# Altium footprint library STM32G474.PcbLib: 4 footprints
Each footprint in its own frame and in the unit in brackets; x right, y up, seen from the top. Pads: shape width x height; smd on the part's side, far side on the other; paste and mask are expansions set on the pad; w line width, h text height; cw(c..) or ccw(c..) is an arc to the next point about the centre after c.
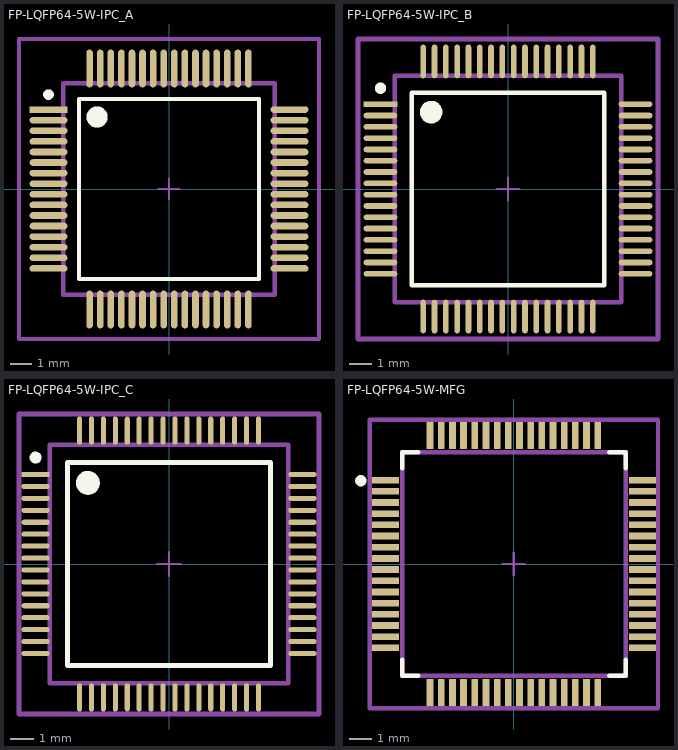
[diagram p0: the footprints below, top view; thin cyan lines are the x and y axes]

## FP-LQFP64-5W-IPC_A [mm]
pads (64):
  rect 1.788x0.312 smd paste+0 mask+0: 1(-5.691,3.75)
  rrect100% 1.788x0.312 smd paste+0 mask+0: 2(-5.691,3.25) 3(-5.691,2.75) 4(-5.691,2.25) 5(-5.691,1.75) 6(-5.691,1.25) 7(-5.691,0.75) 8(-5.691,0.25) 9(-5.691,-0.25) 10(-5.691,-0.75) 11(-5.691,-1.25) 12(-5.691,-1.75) 13(-5.691,-2.25) 14(-5.691,-2.75) 15(-5.691,-3.25) 16(-5.691,-3.75) 33(5.691,-3.75) 34(5.691,-3.25) 35(5.691,-2.75) 36(5.691,-2.25) 37(5.691,-1.75) 38(5.691,-1.25) 39(5.691,-0.75) 40(5.691,-0.25) 41(5.691,0.25) 42(5.691,0.75) 43(5.691,1.25) 44(5.691,1.75) 45(5.691,2.25) 46(5.691,2.75) 47(5.691,3.25) 48(5.691,3.75)
  rrect100% 0.312x1.788 smd paste+0 mask+0: 17(-3.75,-5.691) 18(-3.25,-5.691) 19(-2.75,-5.691) 20(-2.25,-5.691) 21(-1.75,-5.691) 22(-1.25,-5.691) 23(-0.75,-5.691) 24(-0.25,-5.691) 25(0.25,-5.691) 26(0.75,-5.691) 27(1.25,-5.691) 28(1.75,-5.691) 29(2.25,-5.691) 30(2.75,-5.691) 31(3.25,-5.691) 32(3.75,-5.691) 49(3.75,5.691) 50(3.25,5.691) 51(2.75,5.691) 52(2.25,5.691) 53(1.75,5.691) 54(1.25,5.691) 55(0.75,5.691) 56(0.25,5.691) 57(-0.25,5.691) 58(-0.75,5.691) 59(-1.25,5.691) 60(-1.75,5.691) 61(-2.25,5.691) 62(-2.75,5.691) 63(-3.25,5.691) 64(-3.75,5.691)
Top Overlay:
  circle w0.25: c-5.691,4.46 r0.125
  circle w0.5: c-3.4,3.4 r0.25
  lines w0.2: -4.25,-4.25 4.25,-4.25 4.25,4.25 -4.25,4.25 -4.25,-4.25
Top Assembly:
  lines w0.2: -7.085,-7.085 7.085,-7.085 7.085,7.085 -7.085,7.085 -7.085,-7.085
  text ".Designator" at 0,0 h1
Top 3D Body:
  lines w0.2: -5,-5 5,-5 5,5 -5,5 -5,-5
Top Courtyard:
  lines w0.2: -7.085,-7.085 7.085,-7.085 7.085,7.085 -7.085,7.085 -7.085,-7.085
Top Component Center:
  lines w0.1: -0.5,0 0.5,0 ; 0,-0.5 0,0.5
3D body "IC_STMicroelectronics_STM32L431RCT6_eec.STEP": height 0.25, standoff 0, extent -7.085,-7.085 7.085,7.085

## FP-LQFP64-5W-IPC_B [mm]
pads (64):
  rect 1.488x0.252 smd paste+0 mask+0: 1(-5.641,3.75)
  rrect100% 1.488x0.252 smd paste+0 mask+0: 2(-5.641,3.25) 3(-5.641,2.75) 4(-5.641,2.25) 5(-5.641,1.75) 6(-5.641,1.25) 7(-5.641,0.75) 8(-5.641,0.25) 9(-5.641,-0.25) 10(-5.641,-0.75) 11(-5.641,-1.25) 12(-5.641,-1.75) 13(-5.641,-2.25) 14(-5.641,-2.75) 15(-5.641,-3.25) 16(-5.641,-3.75) 33(5.641,-3.75) 34(5.641,-3.25) 35(5.641,-2.75) 36(5.641,-2.25) 37(5.641,-1.75) 38(5.641,-1.25) 39(5.641,-0.75) 40(5.641,-0.25) 41(5.641,0.25) 42(5.641,0.75) 43(5.641,1.25) 44(5.641,1.75) 45(5.641,2.25) 46(5.641,2.75) 47(5.641,3.25) 48(5.641,3.75)
  rrect100% 0.252x1.488 smd paste+0 mask+0: 17(-3.75,-5.641) 18(-3.25,-5.641) 19(-2.75,-5.641) 20(-2.25,-5.641) 21(-1.75,-5.641) 22(-1.25,-5.641) 23(-0.75,-5.641) 24(-0.25,-5.641) 25(0.25,-5.641) 26(0.75,-5.641) 27(1.25,-5.641) 28(1.75,-5.641) 29(2.25,-5.641) 30(2.75,-5.641) 31(3.25,-5.641) 32(3.75,-5.641) 49(3.75,5.641) 50(3.25,5.641) 51(2.75,5.641) 52(2.25,5.641) 53(1.75,5.641) 54(1.25,5.641) 55(0.75,5.641) 56(0.25,5.641) 57(-0.25,5.641) 58(-0.75,5.641) 59(-1.25,5.641) 60(-1.75,5.641) 61(-2.25,5.641) 62(-2.75,5.641) 63(-3.25,5.641) 64(-3.75,5.641)
Top Overlay:
  circle w0.25: c-5.641,4.46 r0.125
  circle w0.5: c-3.4,3.4 r0.25
  lines w0.2: -4.25,-4.25 4.25,-4.25 4.25,4.25 -4.25,4.25 -4.25,-4.25
Top Assembly:
  lines w0.2: -6.635,-6.635 6.635,-6.635 6.635,6.635 -6.635,6.635 -6.635,-6.635
  text ".Designator" at 0,0 h1
Top 3D Body:
  lines w0.2: -5,-5 5,-5 5,5 -5,5 -5,-5
Top Courtyard:
  lines w0.2: -6.635,-6.635 6.635,-6.635 6.635,6.635 -6.635,6.635 -6.635,-6.635
Top Component Center:
  lines w0.1: -0.5,0 0.5,0 ; 0,-0.5 0,0.5
3D body "IC_STMicroelectronics_STM32L431RCT6_eec.STEP": height 0.25, standoff 0, extent -6.635,-6.635 6.635,6.635

## FP-LQFP64-5W-IPC_C [mm]
pads (64):
  rect 1.188x0.212 smd paste+0 mask+0: 1(-5.591,3.75)
  rrect100% 1.188x0.212 smd paste+0 mask+0: 2(-5.591,3.25) 3(-5.591,2.75) 4(-5.591,2.25) 5(-5.591,1.75) 6(-5.591,1.25) 7(-5.591,0.75) 8(-5.591,0.25) 9(-5.591,-0.25) 10(-5.591,-0.75) 11(-5.591,-1.25) 12(-5.591,-1.75) 13(-5.591,-2.25) 14(-5.591,-2.75) 15(-5.591,-3.25) 16(-5.591,-3.75) 33(5.591,-3.75) 34(5.591,-3.25) 35(5.591,-2.75) 36(5.591,-2.25) 37(5.591,-1.75) 38(5.591,-1.25) 39(5.591,-0.75) 40(5.591,-0.25) 41(5.591,0.25) 42(5.591,0.75) 43(5.591,1.25) 44(5.591,1.75) 45(5.591,2.25) 46(5.591,2.75) 47(5.591,3.25) 48(5.591,3.75)
  rrect100% 0.212x1.188 smd paste+0 mask+0: 17(-3.75,-5.591) 18(-3.25,-5.591) 19(-2.75,-5.591) 20(-2.25,-5.591) 21(-1.75,-5.591) 22(-1.25,-5.591) 23(-0.75,-5.591) 24(-0.25,-5.591) 25(0.25,-5.591) 26(0.75,-5.591) 27(1.25,-5.591) 28(1.75,-5.591) 29(2.25,-5.591) 30(2.75,-5.591) 31(3.25,-5.591) 32(3.75,-5.591) 49(3.75,5.591) 50(3.25,5.591) 51(2.75,5.591) 52(2.25,5.591) 53(1.75,5.591) 54(1.25,5.591) 55(0.75,5.591) 56(0.25,5.591) 57(-0.25,5.591) 58(-0.75,5.591) 59(-1.25,5.591) 60(-1.75,5.591) 61(-2.25,5.591) 62(-2.75,5.591) 63(-3.25,5.591) 64(-3.75,5.591)
Top Overlay:
  circle w0.25: c-5.591,4.46 r0.125
  circle w0.5: c-3.4,3.4 r0.25
  lines w0.2: -4.25,-4.25 4.25,-4.25 4.25,4.25 -4.25,4.25 -4.25,-4.25
Top Assembly:
  lines w0.2: -6.285,-6.285 6.285,-6.285 6.285,6.285 -6.285,6.285 -6.285,-6.285
  text ".Designator" at 0,0 h1
Top 3D Body:
  lines w0.2: -5,-5 5,-5 5,5 -5,5 -5,-5
Top Courtyard:
  lines w0.2: -6.285,-6.285 6.285,-6.285 6.285,6.285 -6.285,6.285 -6.285,-6.285
Top Component Center:
  lines w0.1: -0.5,0 0.5,0 ; 0,-0.5 0,0.5
3D body "IC_STMicroelectronics_STM32L431RCT6_eec.STEP": height 0.25, standoff 0, extent -6.285,-6.285 6.285,6.285

## FP-LQFP64-5W-MFG [mm]
pads (64):
  rect 1.2x0.3 smd paste+0 mask+0: 1(-5.75,3.75) 2(-5.75,3.25) 3(-5.75,2.75) 4(-5.75,2.25) 5(-5.75,1.75) 6(-5.75,1.25) 7(-5.75,0.75) 8(-5.75,0.25) 9(-5.75,-0.25) 10(-5.75,-0.75) 11(-5.75,-1.25) 12(-5.75,-1.75) 13(-5.75,-2.25) 14(-5.75,-2.75) 15(-5.75,-3.25) 16(-5.75,-3.75) 33(5.75,-3.75) 34(5.75,-3.25) 35(5.75,-2.75) 36(5.75,-2.25) 37(5.75,-1.75) 38(5.75,-1.25) 39(5.75,-0.75) 40(5.75,-0.25) 41(5.75,0.25) 42(5.75,0.75) 43(5.75,1.25) 44(5.75,1.75) 45(5.75,2.25) 46(5.75,2.75) 47(5.75,3.25) 48(5.75,3.75)
  rect 0.3x1.2 smd paste+0 mask+0: 17(-3.75,-5.75) 18(-3.25,-5.75) 19(-2.75,-5.75) 20(-2.25,-5.75) 21(-1.75,-5.75) 22(-1.25,-5.75) 23(-0.75,-5.75) 24(-0.25,-5.75) 25(0.25,-5.75) 26(0.75,-5.75) 27(1.25,-5.75) 28(1.75,-5.75) 29(2.25,-5.75) 30(2.75,-5.75) 31(3.25,-5.75) 32(3.75,-5.75) 49(3.75,5.75) 50(3.25,5.75) 51(2.75,5.75) 52(2.25,5.75) 53(1.75,5.75) 54(1.25,5.75) 55(0.75,5.75) 56(0.25,5.75) 57(-0.25,5.75) 58(-0.75,5.75) 59(-1.25,5.75) 60(-1.75,5.75) 61(-2.25,5.75) 62(-2.75,5.75) 63(-3.25,5.75) 64(-3.75,5.75)
Top Overlay:
  circle w0.25: c-6.85,3.725 r0.125
  lines w0.2: -5,-4.275 -5,-5 -4.275,-5 ; -5,4.275 -5,5 -4.275,5 ; 4.275,-5 5,-5 5,-4.275 ; 4.275,5 5,5 5,4.275
Top Assembly:
  lines w0.2: -6.45,-6.45 6.45,-6.45 6.45,6.45 -6.45,6.45 -6.45,-6.45
  text ".Designator" at 0,0.188 h1
Top 3D Body:
  lines w0.2: -5,-5 5,-5 5,5 -5,5 -5,-5
Top Courtyard:
  lines w0.2: -6.45,-6.45 6.45,-6.45 6.45,6.45 -6.45,6.45 -6.45,-6.45
Top Component Center:
  lines w0.1: -0.5,0 0.5,0 ; 0,-0.5 0,0.5
3D body "IC_STMicroelectronics_STM32L431RCT6_eec.STEP": height 0.25, standoff 0, extent -6.45,-6.45 6.45,6.45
